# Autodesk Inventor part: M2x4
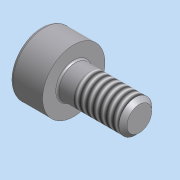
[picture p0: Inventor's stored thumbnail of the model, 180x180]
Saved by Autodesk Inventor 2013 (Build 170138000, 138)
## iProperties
Company: 한국ATC센터
Created: 2015-05
Part Number: M2x4
Document SubType Name: 모델링
Designer: KYOUNG IL JANG
Vendor: CBT Solutions
Material: 일반
Author: KYOUNG IL JANG
Comments: 파생
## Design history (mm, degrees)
node "KS B 1003 - 미터 M 2 x 4" dims "d0" = 10
node "솔리드1"
node "솔리드 본체"
node "곡면 본체"
feature "Solid1::KS B 1003 - 미터 M 2 x 4" dims "d0" = 10
tag "피쳐 태그1"
